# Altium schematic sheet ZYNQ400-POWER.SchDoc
size A3
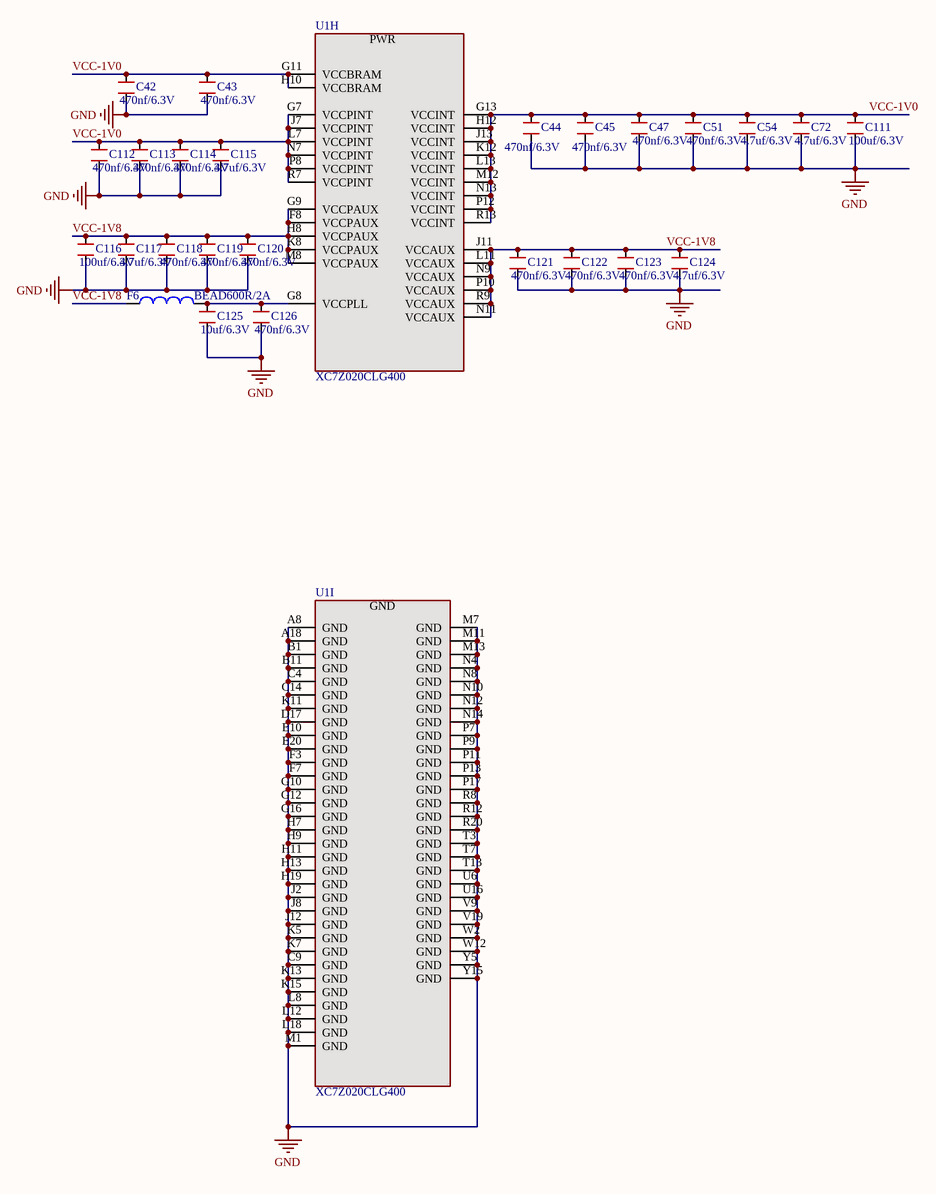
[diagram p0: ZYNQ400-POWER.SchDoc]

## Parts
C42  470nf/6.3V  [0402]
C43  470nf/6.3V  [0402]
C44  470nf/6.3V  [0402]
C45  470nf/6.3V  [0402]
C47  470nf/6.3V  [0402]
C51  470nf/6.3V  [0402]
C54  4.7uf/6.3V  [0402]
C72  4.7uf/6.3V  [0402]
C111  100uf/6.3V  [0805]
C112  470nf/6.3V  [0402]
C113  470nf/6.3V  [0402]
C114  470nf/6.3V  [0402]
C115  4.7uf/6.3V  [0402]
C116  100uf/6.3V  [0805]
C117  4.7uf/6.3V  [0402]
C118  470nf/6.3V  [0402]
C119  470nf/6.3V  [0402]
C120  470nf/6.3V  [0402]
C121  470nf/6.3V  [0402]
C122  470nf/6.3V  [0402]
C123  470nf/6.3V  [0402]
C124  4.7uf/6.3V  [0402]
C125  10uf/6.3V  [0603]
C126  470nf/6.3V  [0402]
F6  BEAD600R/2A  [0603]
U1  XC7Z020CLG400  [CLG400]  (parts H,I of 9)

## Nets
GND: C42.2 C43.2 C44.2 C45.2 C47.2 C51.2 C54.2 C72.2 C111.2 C112.2 C113.2 C114.2 C115.2 C116.2 C117.2 C118.2 C119.2 C120.2 C121.2 C122.2 C123.2 C124.2 C125.2 C126.2 U1.A8(GND) U1.A18(GND) U1.B1(GND) U1.B11(GND) U1.C4(GND) U1.C9(GND) U1.C14(GND) U1.D17(GND) U1.E10(GND) U1.E20(GND) U1.F3(GND) U1.F7(GND) U1.G10(GND) U1.G12(GND) U1.G16(GND) U1.H7(GND) U1.H9(GND) U1.H11(GND) U1.H13(GND) U1.H19(GND) U1.J2(GND) U1.J8(GND) U1.J12(GND) U1.K5(GND) U1.K7(GND) U1.K11(GND) U1.K13(GND) U1.K15(GND) U1.L8(GND) U1.L12(GND) U1.L18(GND) U1.M1(GND) U1.M7(GND) U1.M11(GND) U1.M13(GND) U1.N4(GND) U1.N8(GND) U1.N10(GND) U1.N12(GND) U1.N14(GND) U1.P7(GND) U1.P9(GND) U1.P11(GND) U1.P13(GND) U1.P17(GND) U1.R8(GND) U1.R12(GND) U1.R20(GND) U1.T3(GND) U1.T7(GND) U1.T13(GND) U1.U6(GND) U1.U16(GND) U1.V9(GND) U1.V19(GND) U1.W2(GND) U1.W12(GND) U1.Y5(GND) U1.Y15(GND)
VCC-1V0: C42.1 C43.1 C44.1 C45.1 C47.1 C51.1 C54.1 C72.1 C111.1 C112.1 C113.1 C114.1 C115.1 U1.G7(VCCPINT) U1.G11(VCCBRAM) U1.G13(VCCINT) U1.H10(VCCBRAM) U1.H12(VCCINT) U1.J7(VCCPINT) U1.J13(VCCINT) U1.K12(VCCINT) U1.L7(VCCPINT) U1.L13(VCCINT) U1.M12(VCCINT) U1.N7(VCCPINT) U1.N13(VCCINT) U1.P8(VCCPINT) U1.P12(VCCINT) U1.R7(VCCPINT) U1.R13(VCCINT)
VCC-1V8: C116.1 C117.1 C118.1 C119.1 C120.1 C121.1 C122.1 C123.1 C124.1 F6.1 U1.F8(VCCPAUX) U1.G9(VCCPAUX) U1.H8(VCCPAUX) U1.J11(VCCAUX) U1.K8(VCCPAUX) U1.L11(VCCAUX) U1.M8(VCCPAUX) U1.N9(VCCAUX) U1.N11(VCCAUX) U1.P10(VCCAUX) U1.R9(VCCAUX)
NetC125_1: C125.1 C126.1 F6.2 U1.G8(VCCPLL)

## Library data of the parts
C42-C45 C47 C51 C54 C72 C111-C126 = CAPACITOR: Generic Capacitor
F6 = Inductor: Code_IEC: 1005
U1 = XC7Z020-CLG400: Zynq 7000 FPGA 20 Die, in a CSG 484 Package; Manufacturer: Xilinx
